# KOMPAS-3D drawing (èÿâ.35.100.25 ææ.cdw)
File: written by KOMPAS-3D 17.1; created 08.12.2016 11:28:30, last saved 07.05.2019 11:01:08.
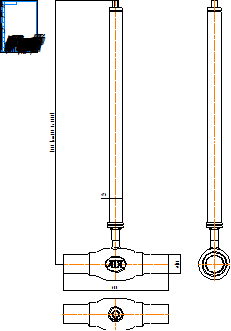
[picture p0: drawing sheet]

Sheet 1: A4, portrait

Title block, sheet 1: name: КШГ.35.100.25 СС; material: Внимание! Данный продукт является объектом авторского права ООО «Торговый Дом АДЛ». / Запрещается изменение, копирование, распространение / (в том числе путем копирования на другие сайты и ресурсы в Интернете) / или любое иное использование информации и объектов без предварительного / согласия правообладателя (ООО «Торговый Дом АДЛ»).; sheets: 1; organisation: ООО "Торговый дом АДЛ"; sheet format: A4; stored path: C:\Users\kka\KOMPAS_Work\Модели кранов для исследований\DN125\С удлинением\КШГ.35.100.25 СС ГЧ _ Шаровой кран БИВАЛ Ду80 Ру2,5 МПа полнопроходной под приварку, c удлинением штока H=1500 Lстр600.cdw; drawn by: Климкович К.А.; drawn by, date: 30.03.17

Views: Вид 1, Проекционный вид 2
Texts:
  Klimkovich
  ADL
  (от 425 до 5000)
Dimensions and other numbers on the sheet: 600; 108; 76; 1500; 1:1; 1; 30.03.17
